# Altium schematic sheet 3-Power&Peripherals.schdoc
size 315 x 219 mm
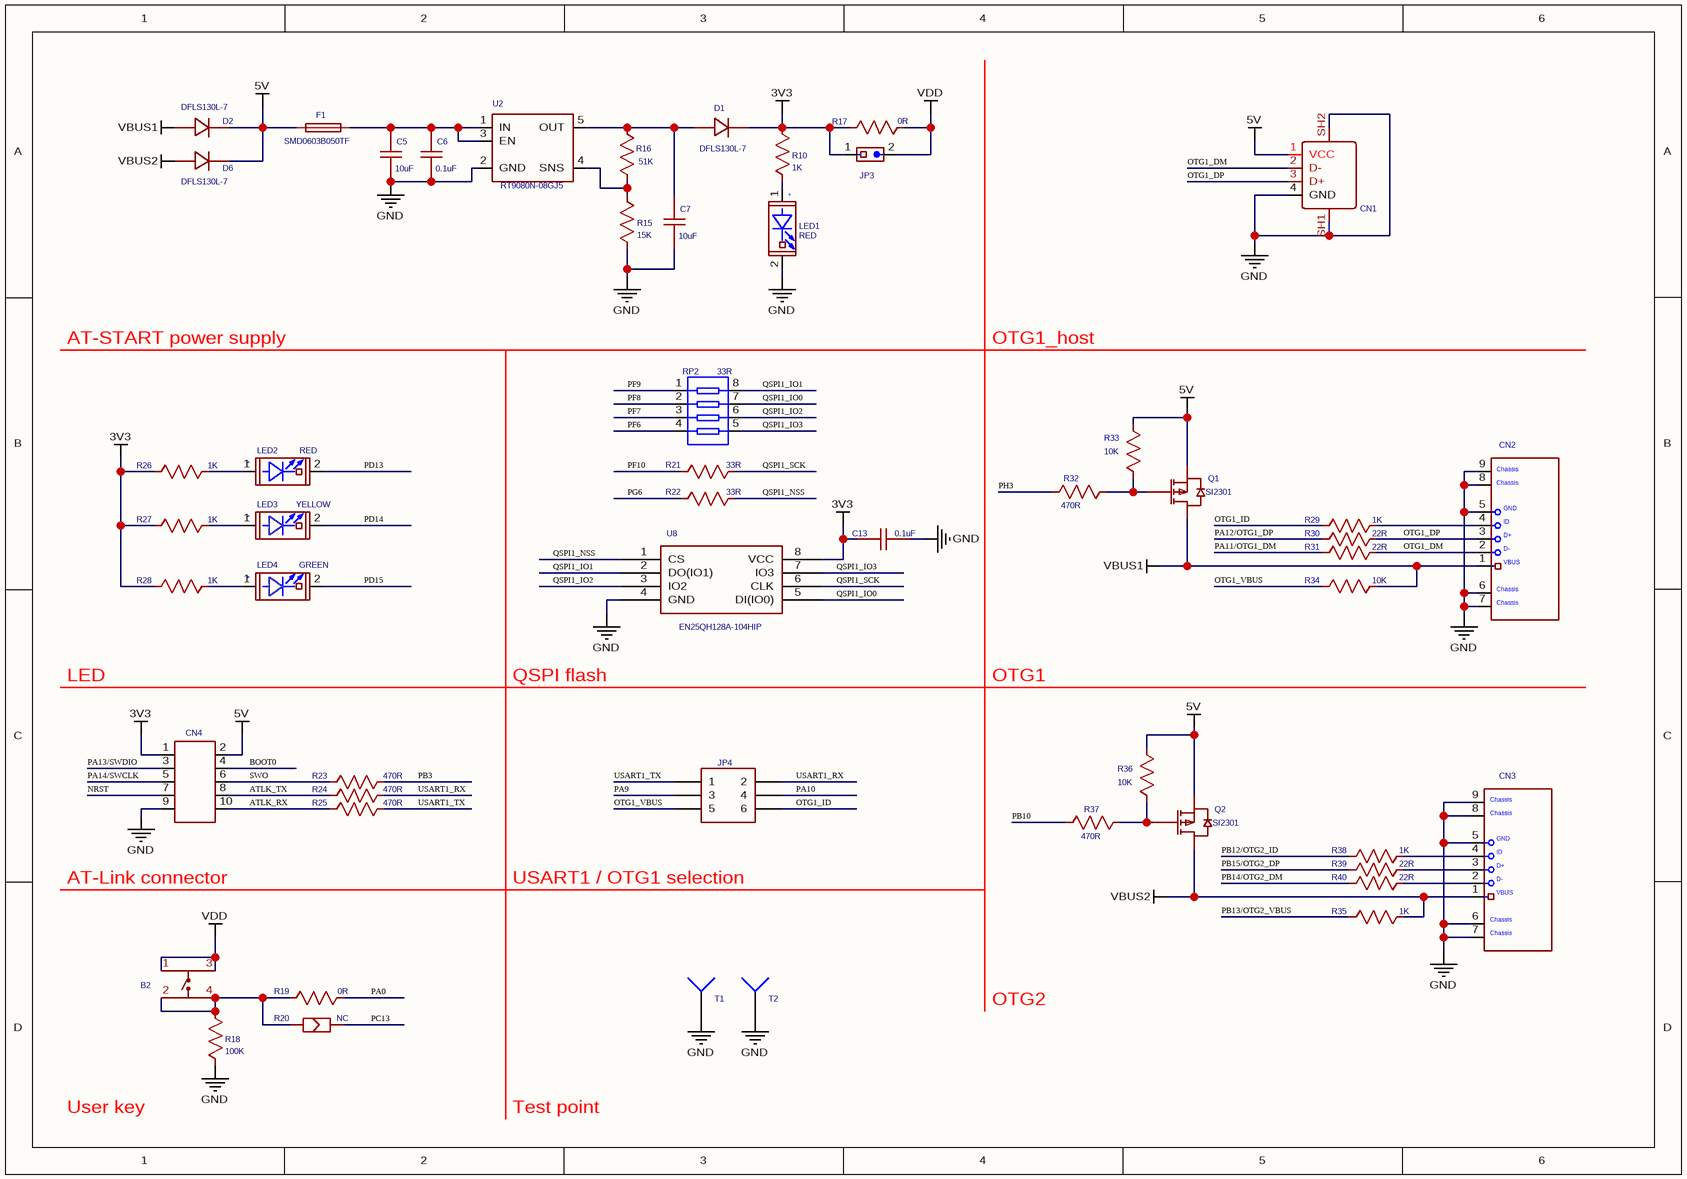
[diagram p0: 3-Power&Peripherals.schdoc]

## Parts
B2  贴片按键 6x6x5mm 蓝色  [SW-SMD_4P-L6.0-W6.0-P4.50-LS9.0]  (value not drawn)
C5  10uF  [0603_C-M]
C6  0.1uF  [0603_C-M]
C7  10uF  [0603_C-M]
C13  0.1uF  [0603_C-M]
CN1  JTJ-USB-AF-08  [USB-A-TH__USB-AF-90]  (value not drawn)
CN2  USB_micro B  [USB_MIC_DIP]  (value not drawn)
CN3  USB_micro B  [USB_MIC_DIP]  (value not drawn)
CN4  直插简易牛角2.54mm，2x5P  [HDR2X5]  (value not drawn)
D1  DFLS130L-7  [POWERDI-123_L2.8-W1.8-LS3.7-RD]
D2  DFLS130L-7  [POWERDI-123_L2.8-W1.8-LS3.7-RD]
D6  DFLS130L-7  [POWERDI-123_L2.8-W1.8-LS3.7-RD]
F1  SMD0603B050TF  [R0603]
JP3  Jumper 1x2P  [HEADER 1X2]  (value not drawn)
JP4  Header 3X2  [HDR2X3]  (value not drawn)
LED1  RED  [LED0603]
LED2  RED  [LED0603]
LED3  YELLOW  [LED0603]
LED4  GREEN  [LED0603]
Q1  SI2301  [SOT-23-3_L2.9-W1.3-P1.90-LS2.4-BR]
Q2  SI2301  [SOT-23-3_L2.9-W1.3-P1.90-LS2.4-BR]
R10  1K  [0603_R-M]
R15  15K  [0603_R-M]
R16  51K  [0603_R-M]
R17  0R  [0603_R-M]
R18  100K  [0603_R-M]
R19  0R  [0603_R-M]
R20  NC  [SB-PAD]
R21  33R  [0603_R-M]
R22  33R  [0603_R-M]
R23  470R  [0603_R-M]
R24  470R  [0603_R-M]
R25  470R  [0603_R-M]
R26  1K  [0603_R-M]
R27  1K  [0603_R-M]
R28  1K  [0603_R-M]
R29  1K  [0603_R-M]
R30  22R  [0603_R-M]
R31  22R  [0603_R-M]
R32  470R  [0603_R-M]
R33  10K  [0603_R-M]
R34  10K  [0603_R-M]
R35  1K  [0603_R-M]
R36  10K  [0603_R-M]
R37  470R  [0603_R-M]
R38  1K  [0603_R-M]
R39  22R  [0603_R-M]
R40  22R  [0603_R-M]
RP2  33R  [0603*4,8P4R]
T1  TESTPOINT TP-5006  [TESTHOOK]  (value not drawn)
T2  TESTPOINT TP-5006  [TESTHOOK]  (value not drawn)
U2  RT9080N-08GJ5  [SOT-23-5]
U8  EN25QH128A-104HIP  [SOIC-8_208MIL]

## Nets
3V3: C13.1 CN4.1 D1.1 JP3.1 R10.1 R17.1 R26.1 R27.1 R28.1 U8.8(VCC)
5V: CN1.1(VCC) CN4.2 D2.1 D6.1 F1.1 Q1.2(S) Q2.2(S) R33.2 R36.2
GND: C5.2 C6.2 C7.2 C13.2 CN1.4(GND) CN1.SH1 CN1.SH2 CN2.5(GND) CN2.6 CN2.7 CN2.8 CN2.9 CN3.5(GND) CN3.6 CN3.7 CN3.8 CN3.9 CN4.9 LED1.2(CATHODE) R15.2 R18.1 T1.1 T2.1 U2.2(GND) U8.4(GND)
VBUS1: CN2.1(VBUS) D2.2 Q1.3(D) R34.2
VBUS2: CN3.1(VBUS) D6.2 Q2.3(D) R35.2
VDD: B2.1 B2.3 JP3.2 R17.2
ATLK_RX: CN4.10 R25.1
ATLK_TX: CN4.8 R24.1
BOOT0: CN4.4
NRST: CN4.7
OTG1_DM: CN1.2(D-) CN2.2(D-) R31.2
OTG1_DP: CN1.3(D+) CN2.3(D+) R30.2
OTG1_ID: JP4.6 R29.1
OTG1_VBUS: JP4.5 R34.1
PA0: R19.2
PA9: JP4.3
PA10: JP4.4
PA11/OTG1_DM: R31.1
PA12/OTG1_DP: R30.1
PA13/SWDIO: CN4.3
PA14/SWCLK: CN4.5
PB3: R23.2
PB10: R37.1
PB12/OTG2_ID: R38.1
PB13/OTG2_VBUS: R35.1
PB14/OTG2_DM: R40.1
PB15/OTG2_DP: R39.1
PC13: R20.2
PD13: LED2.2(CATHODE)
PD14: LED3.2(CATHODE)
PD15: LED4.2(CATHODE)
PF6: RP2.4
PF7: RP2.3
PF8: RP2.2
PF9: RP2.1
PF10: R21.1
PG6: R22.1
PH3: R32.1
QSPI1_IO0: RP2.7 U8.5(DI(IO0))
QSPI1_IO1: RP2.8 U8.2(DO(IO1))
QSPI1_IO2: RP2.6 U8.3(IO2)
QSPI1_IO3: RP2.5 U8.7(IO3)
QSPI1_NSS: R22.2 U8.1(CS)
QSPI1_SCK: R21.2 U8.6(CLK)
SWO: CN4.6 R23.1
USART1_RX: JP4.2 R24.2
USART1_TX: JP4.1 R25.2
NetB2_2: B2.2 B2.4 R18.2 R19.1 R20.1
NetC5_1: C5.1 C6.1 F1.2 U2.1(IN) U2.3(EN)
NetC7_1: C7.1 D1.2 R16.2 U2.5(OUT)
NetCN2_4: CN2.4(ID) R29.2
NetCN3_2: CN3.2(D-) R40.2
NetCN3_3: CN3.3(D+) R39.2
NetCN3_4: CN3.4(ID) R38.2
NetLED1_1: LED1.1(ANODE) R10.2
NetLED2_1: LED2.1(ANODE) R26.2
NetLED3_1: LED3.1(ANODE) R27.2
NetLED4_1: LED4.1(ANODE) R28.2
NetQ1_1: Q1.1(G) R32.2 R33.1
NetQ2_1: Q2.1(G) R36.1 R37.2
NetR15_1: R15.1 R16.1 U2.4(SNS)

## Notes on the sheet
- AT-START power supply
- OTG1_host
- LED
- QSPI flash
- OTG1
- AT-Link connector
- USART1 / OTG1 selection
- OTG2
- User key
- Test point

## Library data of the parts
B2 = 贴片按键 6x6x5mm 蓝色: BOM_Manufacturer: Korean Hroparts Elec; BOM_Manufacturer Part: K2-1102SP-C3SC-04; Contributor: LCSC; BOM_Paste Type: expand
C5 C7 = 10uF: nameAlias: Value(F); Contributor: LCEDA_Lib
C6 C13 = 0.1uF: nameAlias: Value(F); Contributor: LCEDA_Lib
CN1 = JTJ-USB-AF-08: Contributor: LCSC; BOM_Paste Type: expand
CN4 = 直插简易牛角2.54mm，2x5P: Contributor: twb17
D1 D2 D6 = DFLS130L-7: BOM_Manufacturer: Diodes Incorporated; Contributor: LCSC; BOM_Paste Type: expand
F1 = SMD0603B050TF: BOM_Manufacturer: Brightking Elec (TAIWAN); BOM_Manufacturer Part: SMD0603B035TF; Contributor: LCSC; BOM_Paste Type: expand
JP3 = Jumper 1x2P: Contributor: twb17
JP4 = Header 3X2: Contributor: twb17
Q1 Q2 = SI2301: BOM_Manufacturer: FM; BOM_Manufacturer Part: 2301; BOM_Paste Type: recommend
R10 R26-R29 R35 R38 = 1K: nameAlias: Value(Ω); Contributor: LCEDA_Lib
R15 = 15K: nameAlias: Value(Ω); Contributor: LCEDA_Lib
R16 = 51K: nameAlias: Value(Ω); Contributor: LCEDA_Lib
R17 R19 = 0R: nameAlias: Value(Ω); Contributor: LCEDA_Lib
R18 = 100K: nameAlias: Value(Ω); Contributor: LCEDA_Lib
R20 = NC: Contributor: twb17
R21 R22 = 33R: nameAlias: Value(Ω); Contributor: LCEDA_Lib
R23-R25 R32 R37 = 470R: nameAlias: Value(Ω); Contributor: LCEDA_Lib
R30 R31 R39 R40 = 22R: nameAlias: Value(Ω); Contributor: LCEDA_Lib
R33 R34 R36 = 10K: nameAlias: Value(Ω); Contributor: LCEDA_Lib
RP2 = 33R: Contributor: twb17
T1 T2 = TESTPOINT TP-5006: Contributor: twb17
U8 = EN25QH128A-104HIP: Contributor: twb17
